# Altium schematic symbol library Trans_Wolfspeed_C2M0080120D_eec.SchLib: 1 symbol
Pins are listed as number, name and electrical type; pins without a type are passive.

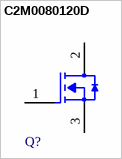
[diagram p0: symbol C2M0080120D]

## C2M0080120D
designator Q?  (value not drawn)
pins: 1 Gate, 2 Drain, 3 Source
